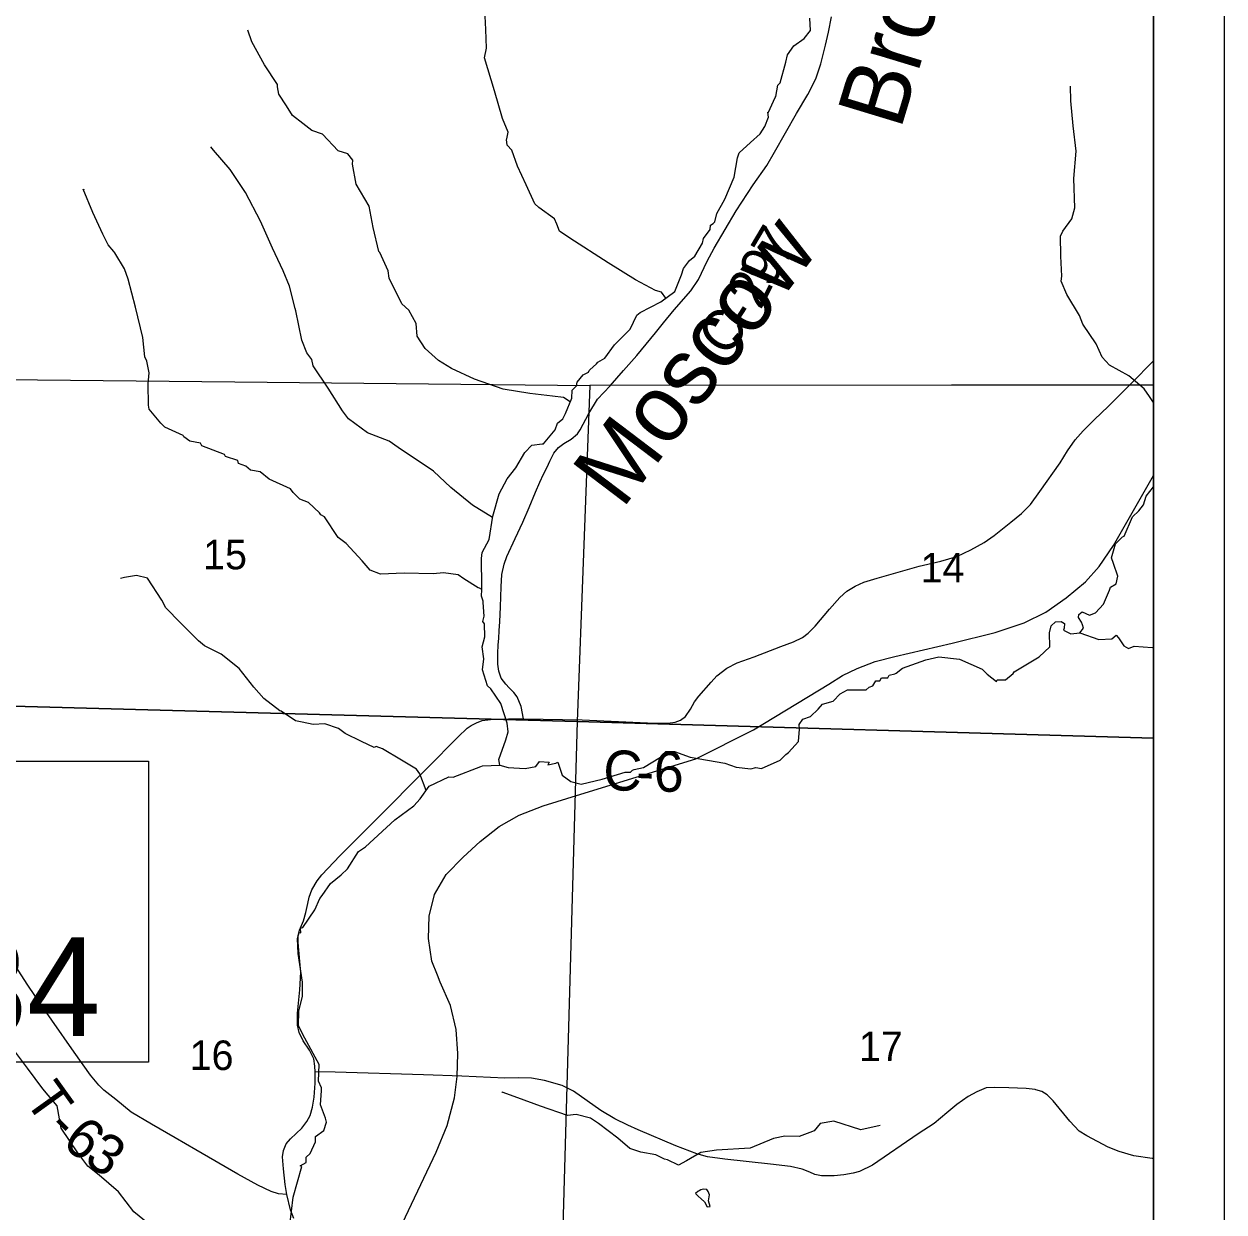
# Model space of a CAD drawing. Extents: x 0 to 34, y 0 to 22.
# Drawn here: x 7.298 to 9, y 17.624 to 19.309 of the extents above; entities that cross this region are included whole.
import ezdxf

# ---------------------------------------------------------------- set-up
doc = ezdxf.new("R2010")
doc.units = 0
for name, color, linetype in [('GM_X_Corporation', 7, 'Continuous'), ('GM_X_County_Road', 7, 'Continuous'), ('GM_X_County_Road_Text', 7, 'Continuous'), ('GM_X_Minor_Lake', 7, 'Continuous'), ('GM_X_Minor_River', 7, 'Continuous'), ('GM_X_Minor_River_Text', 7, 'Continuous'), ('GM_X_Rail_Line', 7, 'Continuous'), ('GM_X_Section_Text', 7, 'Continuous'), ('GM_X_Township_Road', 7, 'Continuous'), ('GM_X_Township_Road_Text', 7, 'Continuous'), ('SH_Data', 7, 'Continuous'), ('SH_Text', 7, 'Continuous')]:
    doc.layers.add(name, color=color, linetype=linetype)

msp = doc.modelspace()

# ---------------------------------------------------------------- linework, layer by layer
at = {"layer": 'GM_X_Corporation'}
msp.add_lwpolyline([(4.9914, 16.3477), (5.6931, 16.3352), (5.9938, 16.3204), (6.9309, 16.303), (7.0302, 16.2995), (7.0491, 16.2993), (8.0233, 16.275), (8.785, 16.2515), (8.9, 16.2485), (8.9, 20.9), (2.1, 20.9)], dxfattribs=at)
for points in [[(8.9, 16.2485), (8.9, 20.9), (7.1302, 20.9), (7.1249, 20.7061), (7.1008, 19.81), (7.0876, 19.4092), (7.0729, 18.3402), (7.0442, 17.0463), (7.0361, 16.5712), (7.0342, 16.5147), (7.0339, 16.4517), (7.0334, 16.423), (7.0337, 16.3927), (7.0306, 16.367), (7.0302, 16.2995), (7.0491, 16.2993), (8.0233, 16.275), (8.785, 16.2515)], [(7.0832, 18.8066), (7.5969, 18.8015), (8.1004, 18.7963), (8.0825, 18.3198), (7.0725, 18.3472)], [(8.9, 18.2958), (8.9, 18.7967), (8.6133, 18.7964), (8.1004, 18.7963), (8.0825, 18.3198)], [(7.0725, 18.3472), (8.0825, 18.3198), (8.0536, 17.3026), (7.0493, 17.3262)], [(8.9, 17.2751), (8.9, 18.2958), (8.0825, 18.3198), (8.0536, 17.3026)]]:
    msp.add_lwpolyline(points, close=True, dxfattribs=at)
at = {"layer": 'GM_X_County_Road'}
for points in [[(8.0061, 18.3236), (8.0027, 18.3407), (7.9973, 18.3548), (7.9926, 18.3608), (7.9857, 18.3675), (7.981, 18.3727), (7.9747, 18.3811), (7.9713, 18.3908), (7.9697, 18.4007), (7.9699, 18.416), (7.9704, 18.4282), (7.9713, 18.4374), (7.9717, 18.4487), (7.9724, 18.4611), (7.9735, 18.4821), (7.9747, 18.5107), (7.9756, 18.5283), (7.9789, 18.5427), (7.9826, 18.5535), (7.9943, 18.5793), (8.0051, 18.6021), (8.0143, 18.6231), (8.0231, 18.6449), (8.0296, 18.6589), (8.0348, 18.6705), (8.0396, 18.6803), (8.0436, 18.6887), (8.0494, 18.7003), (8.056, 18.7083), (8.0634, 18.714), (8.0736, 18.7199), (8.0828, 18.7275), (8.0867, 18.7332), (8.0988, 18.7563), (8.1114, 18.7768), (8.129, 18.7956), (8.1482, 18.8175), (8.1668, 18.8386), (8.1934, 18.871), (8.205, 18.8848), (8.2199, 18.9036), (8.2437, 18.9302), (8.2545, 18.9464), (8.2669, 18.9727), (8.2769, 18.9909), (8.3077, 19.0437), (8.3321, 19.0807), (8.3515, 19.1083), (8.3623, 19.1273), (8.3937, 19.182), (8.4096, 19.209), (8.421, 19.2312), (8.428, 19.2524), (8.4346, 19.2788), (8.4389, 19.2973), (8.4432, 19.3188)], [(7.6804, 17.6147), (7.6757, 17.6272), (7.6705, 17.6488), (7.668, 17.663), (7.6658, 17.6851), (7.6644, 17.702), (7.6658, 17.7112), (7.6696, 17.7207), (7.6755, 17.7275), (7.6917, 17.7428), (7.6989, 17.7523), (7.7034, 17.761), (7.707, 17.7725), (7.7091, 17.787), (7.7106, 17.8066), (7.7106, 17.8228), (7.7102, 17.8307), (7.7086, 17.8411), (7.7025, 17.8535), (7.6937, 17.8666), (7.6879, 17.8785), (7.6858, 17.8891), (7.6858, 17.9058), (7.6888, 17.9392), (7.6901, 17.964), (7.689, 17.9793), (7.6863, 18.0061), (7.6865, 18.0156), (7.6885, 18.0235), (7.6942, 18.037), (7.6976, 18.0487), (7.7001, 18.0615), (7.7021, 18.0704), (7.7057, 18.081), (7.7133, 18.0936), (7.7201, 18.102), (7.7456, 18.129), (7.7959, 18.1793), (7.8696, 18.2532), (7.9137, 18.2979), (7.9265, 18.3099), (7.9318, 18.3139), (7.9393, 18.3175), (7.9477, 18.3209), (7.9634, 18.3227), (7.9848, 18.3234), (8.0061, 18.3236), (8.0892, 18.3221), (8.1819, 18.3179), (8.2109, 18.317), (8.2215, 18.3186), (8.2289, 18.3214), (8.2362, 18.3265), (8.243, 18.3369), (8.249, 18.3474), (8.2551, 18.3556), (8.2726, 18.3756), (8.2804, 18.3842), (8.2948, 18.395), (8.3092, 18.4029), (8.3336, 18.4113), (8.3712, 18.4258), (8.3893, 18.4325), (8.4022, 18.4385), (8.41, 18.4449), (8.42, 18.4546), (8.4402, 18.4787), (8.4551, 18.4954), (8.465, 18.5046), (8.4765, 18.5116), (8.4892, 18.5173), (8.5079, 18.5231), (8.5676, 18.54), (8.5985, 18.5472), (8.6211, 18.5535), (8.6409, 18.5632), (8.6596, 18.5734), (8.674, 18.5835), (8.6975, 18.6022), (8.7128, 18.6144), (8.7257, 18.6273), (8.7388, 18.6458), (8.7678, 18.6863), (8.7782, 18.7035), (8.7888, 18.7193), (8.8001, 18.7319), (8.8161, 18.7477), (8.8357, 18.7662), (8.8682, 18.7989), (8.9, 18.8312)], [(8.7319, 17.7975), (8.7195, 17.7993), (8.6947, 17.8002), (8.6741, 17.8006), (8.6625, 17.8), (8.6492, 17.7945), (8.6369, 17.7877), (8.6209, 17.7763), (8.6069, 17.7647), (8.5887, 17.7493), (8.5659, 17.7349), (8.5012, 17.6904), (8.4829, 17.6813), (8.4741, 17.679), (8.4605, 17.6764), (8.4469, 17.6753), (8.4289, 17.675), (8.4193, 17.6772), (8.4125, 17.6805), (8.4017, 17.6845), (8.3849, 17.6884), (8.3568, 17.6919), (8.2917, 17.6989), (8.2674, 17.702), (8.2521, 17.7062), (8.2223, 17.7178), (8.169, 17.7404), (8.1543, 17.7469), (8.1357, 17.7561), (8.1158, 17.768), (8.077, 17.7954), (8.0612, 17.8035), (8.0358, 17.8105), (8.0174, 17.8138), (7.9994, 17.8144), (7.9795, 17.8136), (7.9185, 17.8165), (7.8642, 17.8183), (7.7388, 17.8224), (7.7106, 17.8228)], [(8.9, 17.6996), (8.8979, 17.6998), (8.8723, 17.7035), (8.8514, 17.7095), (8.8359, 17.7158), (8.8052, 17.7318), (8.7947, 17.7386), (8.7815, 17.7526), (8.7576, 17.7818), (8.7489, 17.7903), (8.7414, 17.7949), (8.7329, 17.7973), (8.7319, 17.7975)]]:
    msp.add_lwpolyline(points, dxfattribs=at)
at = {"layer": 'GM_X_Minor_Lake'}
msp.add_line((8.258, 17.6555), (8.2553, 17.654), dxfattribs=at)
msp.add_lwpolyline([(8.2553, 17.654), (8.2534, 17.6532), (8.2504, 17.6502), (8.2542, 17.6464), (8.2583, 17.6426), (8.2629, 17.6384), (8.267, 17.6312), (8.2708, 17.6319), (8.2685, 17.6399), (8.2701, 17.6482), (8.2682, 17.6528), (8.2663, 17.6558), (8.2614, 17.6562), (8.258, 17.6555)], dxfattribs=at)
at = {"layer": 'GM_X_Minor_River'}
for points in [[(7.9728, 18.2578), (7.971, 18.2658), (7.9809, 18.2934), (7.9843, 18.3047), (7.9832, 18.3172), (7.9742, 18.3449), (7.9599, 18.3658), (7.9549, 18.3703), (7.9478, 18.3927), (7.9497, 18.4086), (7.9475, 18.4257), (7.9513, 18.4397), (7.951, 18.4579), (7.9484, 18.4616), (7.9506, 18.4688), (7.9488, 18.4885), (7.9488, 18.4904), (7.9466, 18.4973), (7.9473, 18.5066), (7.947, 18.5098), (7.9473, 18.5117), (7.9467, 18.5507), (7.9475, 18.5594), (7.9573, 18.5775), (7.9627, 18.6108), (7.9715, 18.6426), (7.9829, 18.6638), (7.9954, 18.6793), (8.0079, 18.7013), (8.0178, 18.7115), (8.0329, 18.7133), (8.0344, 18.7133), (8.0511, 18.7333), (8.0545, 18.7428), (8.0621, 18.7488), (8.0656, 18.7564), (8.0747, 18.778), (8.0751, 18.7897), (8.0815, 18.7958), (8.0823, 18.8011), (8.091, 18.8113), (8.0986, 18.815), (8.0993, 18.8175), (8.1005, 18.8184), (8.1096, 18.8267), (8.1115, 18.829), (8.1217, 18.835), (8.1354, 18.8536), (8.1574, 18.8759), (8.1669, 18.8959), (8.1718, 18.8997), (8.2009, 18.9148), (8.221, 18.9295), (8.2302, 18.9529), (8.2332, 18.962), (8.2419, 18.9734), (8.2495, 18.9794), (8.2601, 18.998), (8.2617, 19.0048), (8.2712, 19.0172), (8.2716, 19.0237), (8.2753, 19.026), (8.2776, 19.0282), (8.2807, 19.04), (8.2917, 19.0604), (8.305, 19.0914), (8.31, 19.1191), (8.3123, 19.1263), (8.3282, 19.141), (8.3418, 19.1531), (8.3487, 19.1637), (8.3536, 19.1766), (8.3529, 19.1838), (8.354, 19.1838), (8.3631, 19.2046), (8.3643, 19.2061), (8.367, 19.222), (8.3704, 19.2254), (8.3784, 19.2549), (8.3807, 19.2652), (8.3898, 19.278), (8.4046, 19.2882), (8.4133, 19.2996), (8.4122, 19.317)], [(8.208, 18.9199), (8.2021, 18.9284), (8.1934, 18.9307), (8.1651, 18.9459), (8.1262, 18.9703), (8.0718, 19.0049), (8.0571, 19.0152), (8.0534, 19.0251), (8.05, 19.0323), (8.0281, 19.0486), (8.0224, 19.0536), (8.01, 19.0809), (7.9976, 19.1071), (7.9897, 19.1299), (7.9829, 19.1371), (7.9822, 19.145), (7.9826, 19.1462), (7.9845, 19.1553), (7.9762, 19.1746), (7.965, 19.2141), (7.9507, 19.2611), (7.9538, 19.2744), (7.9527, 19.3009), (7.9516, 19.3198)], [(8.0726, 18.773), (8.063, 18.7791), (8.0475, 18.7811), (8.015, 18.785), (7.9775, 18.7908), (7.9367, 18.8049), (7.9039, 18.8201), (7.8857, 18.8316), (7.8665, 18.8487), (7.8552, 18.8661), (7.8541, 18.8843), (7.8436, 18.9029), (7.8338, 18.912), (7.8157, 18.9485), (7.8142, 18.9587), (7.8022, 18.9849), (7.801, 18.986), (7.7928, 19.0202), (7.7872, 19.0505), (7.7688, 19.0816), (7.7635, 19.1101), (7.7643, 19.1157), (7.7568, 19.1245), (7.7432, 19.1291), (7.7209, 19.1526), (7.7058, 19.1576), (7.693, 19.1675), (7.6786, 19.1789), (7.67, 19.1926), (7.6591, 19.2093), (7.6572, 19.2199), (7.6572, 19.2229), (7.6387, 19.251), (7.6207, 19.2837), (7.615, 19.3)], [(8.9, 18.7721), (8.8941, 18.7805), (8.8866, 18.7912), (8.8651, 18.8098), (8.8375, 18.825), (8.827, 18.8364), (8.8187, 18.855), (8.7998, 18.8831), (8.795, 18.8952), (8.7769, 18.9252), (8.769, 18.9442), (8.7698, 18.951), (8.7683, 18.9798), (8.768, 19.0082), (8.7703, 19.0128), (8.7714, 19.015), (8.784, 19.0324), (8.7885, 19.048), (8.7871, 19.0896), (8.7903, 19.1283), (8.7858, 19.1643), (8.7825, 19.1999), (8.7822, 19.2208)], [(7.9624, 18.6087), (7.934, 18.6265), (7.9031, 18.6516), (7.8785, 18.6747), (7.8283, 18.7082), (7.8155, 18.717), (7.7849, 18.7288), (7.7577, 18.749), (7.7494, 18.7604), (7.7291, 18.7922), (7.7076, 18.8241), (7.7057, 18.8332), (7.6986, 18.8423), (7.6918, 18.8605), (7.6832, 18.9022), (7.6821, 18.9053), (7.6742, 18.9368), (7.6652, 18.9588), (7.6502, 18.991), (7.6333, 19.029), (7.6118, 19.0699), (7.59, 19.1026), (7.5662, 19.13), (7.5624, 19.1345)], [(7.9473, 18.5066), (7.9436, 18.5086), (7.9417, 18.5094), (7.9217, 18.522), (7.9134, 18.5277), (7.8929, 18.5304), (7.8782, 18.5289), (7.837, 18.5298), (7.8033, 18.5284), (7.7886, 18.5341), (7.7773, 18.5474), (7.7546, 18.5721), (7.7433, 18.5804), (7.7237, 18.61), (7.7188, 18.6127), (7.7169, 18.6154), (7.7011, 18.6302), (7.689, 18.6351), (7.6792, 18.6443), (7.6758, 18.6496), (7.6452, 18.6633), (7.6324, 18.6736), (7.6188, 18.6759), (7.6124, 18.6816), (7.6018, 18.6854), (7.601, 18.6899), (7.5836, 18.6953), (7.5821, 18.6983), (7.55, 18.7105), (7.5478, 18.7143), (7.5327, 18.7174), (7.5243, 18.7231), (7.5232, 18.7254), (7.4975, 18.7372), (7.4915, 18.7429), (7.4753, 18.7627), (7.4742, 18.7684), (7.4739, 18.7983), (7.475, 18.8142), (7.472, 18.8305), (7.469, 18.8366), (7.4661, 18.8642), (7.4556, 18.9071), (7.4451, 18.9469), (7.4399, 18.9617), (7.4263, 18.9841), (7.4252, 18.986), (7.4169, 18.9955), (7.4094, 19.011), (7.3951, 19.0414), (7.3815, 19.0748), (7.383, 19.074)], [(8.0609, 18.2435), (8.0734, 18.2344), (8.0881, 18.2306), (8.1176, 18.2377), (8.1502, 18.2478), (8.1581, 18.2478), (8.1607, 18.2508), (8.163, 18.2516), (8.1763, 18.2542), (8.2005, 18.2689), (8.2081, 18.2772), (8.2202, 18.2772), (8.2428, 18.2691), (8.292, 18.2607), (8.3079, 18.2549), (8.3286, 18.2526), (8.3358, 18.2545), (8.3438, 18.2529), (8.3703, 18.2646), (8.3786, 18.2729), (8.382, 18.2755), (8.3964, 18.291), (8.3976, 18.3088), (8.3972, 18.3153), (8.4025, 18.3228), (8.4135, 18.3266), (8.4241, 18.3372), (8.4302, 18.344), (8.4453, 18.3485), (8.4556, 18.359), (8.4658, 18.3643), (8.4923, 18.3646), (8.4968, 18.3684), (8.5017, 18.3703), (8.5059, 18.3771), (8.5116, 18.3771), (8.5142, 18.3816), (8.5229, 18.3816), (8.5248, 18.3853), (8.5328, 18.3872), (8.5351, 18.3883), (8.5438, 18.3951), (8.5771, 18.4072), (8.5952, 18.4113), (8.6247, 18.4082), (8.6568, 18.3937), (8.664, 18.3865), (8.6772, 18.3762), (8.678, 18.3785), (8.6901, 18.3788), (8.7011, 18.3875), (8.7022, 18.3898), (8.7378, 18.4112), (8.753, 18.4256), (8.7526, 18.4453), (8.7549, 18.4555), (8.761, 18.4608), (8.7689, 18.4615), (8.7735, 18.4585), (8.7734, 18.452), (8.7723, 18.449), (8.7829, 18.4437), (8.7957, 18.4455), (8.8007, 18.452), (8.7992, 18.4569), (8.7977, 18.4607), (8.7935, 18.4671), (8.7939, 18.4713), (8.7988, 18.4751), (8.8094, 18.4705), (8.8177, 18.4739), (8.8291, 18.486), (8.8375, 18.506), (8.839, 18.5102), (8.847, 18.5147), (8.8496, 18.5257), (8.8432, 18.5439), (8.8406, 18.5515), (8.846, 18.5715), (8.8558, 18.5814), (8.8585, 18.5825), (8.8703, 18.6101), (8.879, 18.6184), (8.8858, 18.6267), (8.8896, 18.6392), (8.9, 18.6525)], [(7.868, 18.2215), (7.859, 18.2453), (7.8545, 18.2521), (7.8333, 18.2647), (7.8061, 18.2806), (7.7974, 18.2841), (7.7944, 18.2826), (7.7763, 18.2913), (7.7532, 18.3024), (7.7438, 18.3096), (7.7245, 18.3161), (7.7079, 18.3154), (7.692, 18.3185), (7.6829, 18.3204), (7.6622, 18.3341), (7.6607, 18.3349), (7.638, 18.3523), (7.6237, 18.3683), (7.6026, 18.3949), (7.5773, 18.415), (7.5535, 18.4268), (7.5452, 18.434), (7.5195, 18.4595), (7.4988, 18.4808), (7.4932, 18.4918), (7.4728, 18.5229), (7.4573, 18.5267), (7.4399, 18.5237), (7.4346, 18.5222)], [(8.7957, 18.4455), (8.8222, 18.436), (8.8407, 18.4367), (8.8472, 18.442), (8.8505, 18.4382), (8.8577, 18.4268), (8.8645, 18.423), (8.8724, 18.4264), (8.8982, 18.4244), (8.9, 18.4251)], [(7.6748, 17.6053), (7.6794, 17.6451), (7.6916, 17.6886), (7.6894, 17.6894), (7.6977, 17.6939), (7.6981, 17.7018), (7.7034, 17.7068), (7.711, 17.7234), (7.711, 17.731), (7.7228, 17.7393), (7.7266, 17.7514), (7.7251, 17.7571), (7.7183, 17.776), (7.7195, 17.7961), (7.7195, 17.7999), (7.7154, 17.8094), (7.7162, 17.8329), (7.6962, 17.8704), (7.6872, 17.8879), (7.6873, 17.9091), (7.6926, 17.9295), (7.6926, 17.95), (7.6863, 17.9905), (7.6856, 18.0117), (7.6879, 18.0204), (7.6902, 18.0197), (7.6898, 18.0265), (7.6932, 18.0276), (7.7103, 18.0526), (7.7171, 18.0684), (7.7205, 18.0726), (7.7323, 18.0896), (7.7475, 18.1021), (7.7566, 18.1104), (7.7721, 18.1353), (7.782, 18.1417), (7.8237, 18.1802), (7.8506, 18.1998), (7.8596, 18.21), (7.8725, 18.2278), (7.9002, 18.241), (7.9062, 18.2406), (7.9456, 18.256), (7.9482, 18.2567), (7.9728, 18.2578), (7.9845, 18.2544), (8.0084, 18.2528), (8.0239, 18.2558), (8.0288, 18.2629), (8.0424, 18.2618), (8.0409, 18.258), (8.0519, 18.2606), (8.0549, 18.2617), (8.0609, 18.2435)], [(7.4736, 17.6074), (7.4536, 17.6242), (7.4314, 17.6526), (7.4042, 17.6762), (7.388, 17.6891), (7.374, 17.7077), (7.3503, 17.7427), (7.3447, 17.7745), (7.3244, 17.7984), (7.3025, 17.828), (7.2855, 17.8504)], [(8.5123, 17.7464), (8.4847, 17.7404), (8.4465, 17.7526), (8.4272, 17.7493), (8.4185, 17.7391), (8.4125, 17.7365), (8.3973, 17.7312), (8.3769, 17.7313), (8.361, 17.7283), (8.3277, 17.7144), (8.2801, 17.7115), (8.2577, 17.7085), (8.2373, 17.6964), (8.2259, 17.6904), (8.2105, 17.698), (8.2063, 17.6988), (8.1938, 17.7049), (8.1727, 17.7088), (8.1572, 17.7141), (8.1398, 17.7286), (8.1126, 17.7495), (8.1013, 17.7571), (8.0809, 17.7624), (8.0684, 17.7606), (8.0303, 17.774), (7.9982, 17.7858), (7.9759, 17.7938), (7.9755, 17.7934)]]:
    msp.add_lwpolyline(points, dxfattribs=at)
at = {"layer": 'GM_X_Rail_Line'}
msp.add_lwpolyline([(7.8036, 17.5434), (7.8821, 17.7088), (7.8978, 17.7468), (7.9083, 17.786), (7.9122, 17.8161), (7.9129, 17.8488), (7.9109, 17.8828), (7.9024, 17.9168), (7.888, 17.9501), (7.8842, 17.9597), (7.8762, 17.9796), (7.8716, 18.0116), (7.8723, 18.0437), (7.8801, 18.0744), (7.8965, 18.1025), (7.9207, 18.1273), (7.9449, 18.1496), (7.9717, 18.1705), (7.9999, 18.1868), (8.0339, 18.1999), (8.0875, 18.2163), (8.2505, 18.2666), (8.3323, 18.3078), (8.4396, 18.3725), (8.4586, 18.3849), (8.4795, 18.3948), (8.505, 18.4046), (8.5332, 18.4118), (8.6143, 18.4307), (8.6752, 18.4458), (8.7164, 18.4595), (8.7472, 18.4745), (8.776, 18.4948), (8.8035, 18.5177), (8.8231, 18.5393), (8.8434, 18.5694), (8.9, 18.6687)], dxfattribs=at)
at = {"layer": 'GM_X_Township_Road'}
msp.add_lwpolyline([(7.6705, 17.6488), (7.6586, 17.6497), (7.6484, 17.6531), (7.6292, 17.6621), (7.6011, 17.6776), (7.5411, 17.7119), (7.512, 17.729), (7.4785, 17.7487), (7.4496, 17.7656), (7.4277, 17.7836), (7.4109, 17.7966), (7.4039, 17.8039), (7.3921, 17.818), (7.3688, 17.8508), (7.3369, 17.8962), (7.322, 17.9179), (7.3028, 17.9456), (7.285, 17.9733)], dxfattribs=at)
at = {"layer": 'SH_Data'}
for p, q in [((9, 21), (9, 14)), ((8.9, 20.9), (8.9, 14.1))]:
    msp.add_line(p, q, dxfattribs=at)
at = {"layer": 'SH_Text'}
msp.add_lwpolyline([(6.1555, 18.2631), (7.474, 18.2631), (7.474, 17.8363), (6.1555, 17.8363)], close=True, dxfattribs=at)

# ---------------------------------------------------------------- texts
at = {"layer": 'GM_X_County_Road_Text'}
for s, rotation, p in [('7', 59.3495, (8.3751, 18.9629)), ('9', 60.2822, (8.3578, 18.9327)), ('2', 63.5379, (8.3426, 18.9021)), ('C', 50.5142, (8.2927, 18.8347)), ('-', 57.174, (8.3266, 18.8765)), ('C', 357.4075, (8.1183, 18.2229)), ('6', 0.3229, (8.1913, 18.2198)), ('-', 357.7365, (8.1652, 18.2208))]:
    msp.add_text(s, height=0.0568, rotation=rotation, dxfattribs=at).set_placement(p)
at = {"layer": 'GM_X_Minor_River_Text'}
for s, height, rotation, p in [('Brook', 0.09466, 73.1332, (8.5409, 19.1573)), ('Moscow', 0.09464, 52.8386, (8.1463, 18.6195))]:
    msp.add_text(s, height=height, rotation=rotation, dxfattribs=at).set_placement(p)
at = {"layer": 'GM_X_Section_Text'}
for s, p in [('15', (7.5516, 18.5354)), ('14', (8.5695, 18.5168)), ('17', (8.482, 17.8379)), ('16', (7.5325, 17.8253))]:
    msp.add_text(s, height=0.04186, rotation=0, dxfattribs=at).set_placement(p)
at = {"layer": 'GM_X_Township_Road_Text'}
for s, rotation, p in [('T', 305.6338, (7.2969, 17.783)), ('-', 314.16, (7.3276, 17.7414)), ('6', 321.2117, (7.3495, 17.7195)), ('3', 325.777, (7.3808, 17.6947))]:
    msp.add_text(s, height=0.0568, rotation=rotation, dxfattribs=at).set_placement(p)
at = {"layer": 'SH_Text'}
msp.add_text('COS-60-01.34', height=0.14, dxfattribs=at).set_placement((6.199, 17.8736))

doc.saveas('drawing.dxf')
